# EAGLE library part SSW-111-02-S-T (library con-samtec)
THROUGH-HOLE .025" SQ POST SOCKET Source: Samtec SSW.pdf
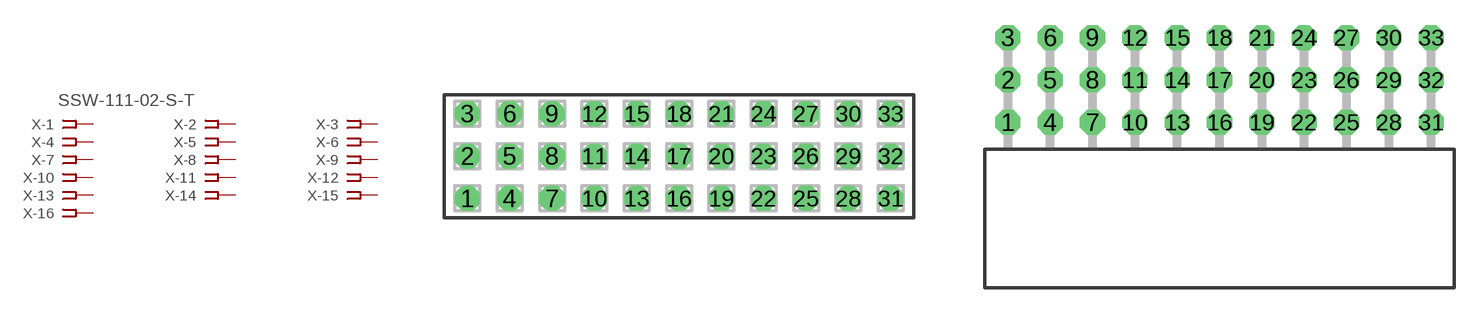
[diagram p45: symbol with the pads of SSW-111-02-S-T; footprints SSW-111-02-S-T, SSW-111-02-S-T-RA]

Designator prefix X; gates -1=FPINV -2=FPIN -3=FPIN -4=FPIN -5=FPIN -6=FPIN -7=FPIN -8=FPIN -9=FPIN -10=FPIN -11=FPIN -12=FPIN -13=FPIN -14=FPIN -15=FPIN -16=FPIN -17=FPIN -18=FPIN -19=FPIN -20=FPIN -21=FPIN -22=FPIN -23=FPIN -24=FPIN -25=FPIN -26=FPIN -27=FPIN -28=FPIN -29=FPIN -30=FPIN -31=FPIN -32=FPIN -33=FPIN

## SSW-111-02-S-T (MPN: SSW-111-02-S-T; OC_FARNELL: unknown; OC_NEWARK: 82P5676)  [SSW-111-02-S-T]
1  -1:1  pas
2  -2:1  pas
3  -3:1  pas
4  -4:1  pas
5  -5:1  pas
6  -6:1  pas
7  -7:1  pas
8  -8:1  pas
9  -9:1  pas
10  -10:1  pas
11  -11:1  pas
12  -12:1  pas
13  -13:1  pas
14  -14:1  pas
15  -15:1  pas
16  -16:1  pas
17  -17:1  pas
18  -18:1  pas
19  -19:1  pas
20  -20:1  pas
21  -21:1  pas
22  -22:1  pas
23  -23:1  pas
24  -24:1  pas
25  -25:1  pas
26  -26:1  pas
27  -27:1  pas
28  -28:1  pas
29  -29:1  pas
30  -30:1  pas
31  -31:1  pas
32  -32:1  pas
33  -33:1  pas

## SSW-111-02-S-TRA (MPN: SSW-111-02-S-T-RA; OC_FARNELL: unknown; OC_NEWARK: 82P5677)  [SSW-111-02-S-T-RA]
Pads as for SSW-111-02-S-T

## Footprint SSW-111-02-S-T (pad centres in mm)
THROUGH-HOLE .025" SQ POST SOCKET Source: Samtec SSW.pdf
drill 1 pad 1.5 octagon: 1 -12.7,-2.54; 2 -12.7,0; 3 -12.7,2.54; 4 -10.16,-2.54; 5 -10.16,0; 6 -10.16,2.54; 7 -7.62,-2.54; 8 -7.62,0; 9 -7.62,2.54; 10 -5.08,-2.54; 11 -5.08,0; 12 -5.08,2.54; 13 -2.54,-2.54; 14 -2.54,0; 15 -2.54,2.54; 16 0,-2.54; 17 0,0; 18 0,2.54; 19 2.54,-2.54; 20 2.54,0; 21 2.54,2.54; 22 5.08,-2.54; 23 5.08,0; 24 5.08,2.54; 25 7.62,-2.54; 26 7.62,0; 27 7.62,2.54; 28 10.16,-2.54; 29 10.16,0; 30 10.16,2.54; 31 12.7,-2.54; 32 12.7,0; 33 12.7,2.54

## Footprint SSW-111-02-S-T-RA (pad centres in mm)
THROUGH-HOLE .025" SQ POST SOCKET Source: Samtec SSW.pdf
drill 1 pad 1.5 octagon: 1 -12.7,1.524; 2 -12.7,4.064; 3 -12.7,6.604; 4 -10.16,1.524; 5 -10.16,4.064; 6 -10.16,6.604; 7 -7.62,1.524; 8 -7.62,4.064; 9 -7.62,6.604; 10 -5.08,1.524; 11 -5.08,4.064; 12 -5.08,6.604; 13 -2.54,1.524; 14 -2.54,4.064; 15 -2.54,6.604; 16 0,1.524; 17 0,4.064; 18 0,6.604; 19 2.54,1.524; 20 2.54,4.064; 21 2.54,6.604; 22 5.08,1.524; 23 5.08,4.064; 24 5.08,6.604; 25 7.62,1.524; 26 7.62,4.064; 27 7.62,6.604; 28 10.16,1.524; 29 10.16,4.064; 30 10.16,6.604; 31 12.7,1.524; 32 12.7,4.064; 33 12.7,6.604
